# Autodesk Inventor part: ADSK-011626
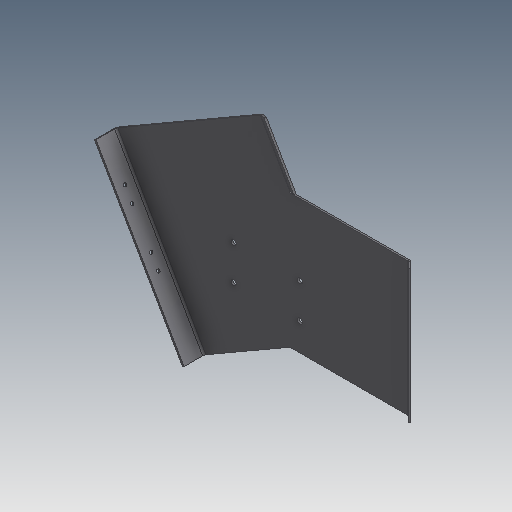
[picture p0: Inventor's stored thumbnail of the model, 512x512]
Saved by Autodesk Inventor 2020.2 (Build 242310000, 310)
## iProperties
Created: 2000-02
Part Number: ADSK-011626
Description: FSHTPH,SS,CP,01,204,165,016,LONG SIDE PAN
Document SubType Name: Tôlerie
Designer: sspink
Material: 1.0312 DC05
Density: 1 g/cm^3
Sheet Metal Rule: Stahlblech 1.0312 - DC05 -   3.0 mm
Appearance: Metal-Steel(Polish)
Mass: 416.174 g
Surface Area: 2829.69 cm^2
Volume: 416.174 cm^3
Flat Pattern Width: 41.2711 cm
Flat Pattern Length: 51.1016 cm
Flat Pattern Area: 2109.02 cm^2
Sheet Metal Width: 16,248 in
Sheet Metal Length: 20,119 in
Sheet Metal Area: 326,899 in^2
Control State: 0
Master: False
Checked Out: False
Shininess: 57.0
Length Units: 11272
Angle Units: 11279
Time Units: 11290
Mass Units: 11286
Length Display Precision: 3
Angle Display Precision: 2
Compacted: True
Cutlength: 17.31 X 21.83  (378 SI)
Material Desc: SHEET,S/S,11 GAUGE,#2B
Material_Number: A084638
G_L: 16,2x20,1 in
Thickness: 0,118 in
Dimensions: 16,5x1,5x20,4 in
Mass: 0,918 lb
Semi finished: Stahlblech 1.0312 - DC05 -   3.0 mm
VLT_Material: 1.0312 DC05
Density: 8.03
Volumn: 445.93185799515726
Area: 2866.578471941887
PropertySet Name: Model Information
Author: sspink
Revision Number: -
Title: FSHTPH,SS,CP,01,204,165,016,LONG SIDE PAN
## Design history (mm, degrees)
derived "ADSK-011625.ipt"
node "Solide1"
node "Corps solides"
node "Corps surfaciques"
feature "Solide1::ADSK-011625.ipt" dims "d53" = 10
tag "Bezeichnung1"
node "Volumenkörper2"
feature "Definition1"
other parameters: "Thickness" = 3 (derived), "BendRadius" = 3 (= Thickness), "BendReliefWidth" = 3 (= Thickness), "BendReliefDepth" = 1.5 (= 0.5 x Thickness), "CornerReliefSize" = 12 (= 4 x Thickness), "SeamGap" = 0.00508, "MinimumRemnant" = 6 (= 2 x Thickness), "d2" = 3 (= BendRadius), "TransitionRadius" = 3 (= BendRadius), "TailleRayonJacobi" = 3 (= BendRadius), "TailleJeu" = 3 (= Thickness), "d54" = 3 (= Thickness), "BendRadius" = 3, "BendReliefDepth" = 1.5, "BendReliefWidth" = 3, "CornerReliefSize" = 12, "MinimumRemnant" = 6, "TailleJeu" = 3, "TailleRayonJacobi" = 3, "Thickness" = 3, "TransitionRadius" = 3
